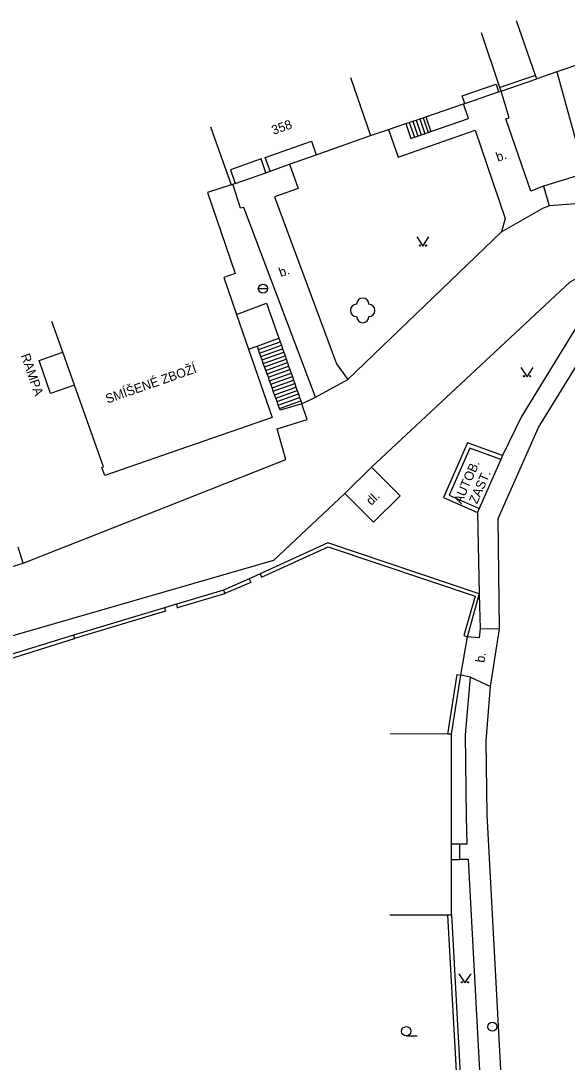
# Model space of a CAD drawing. Extents: x -582162 to -561283, y -1187583 to -1183539.
# Drawn here: x -575012.8 to -574968.4, y -1183822 to -1183737.3 of the extents above; entities that cross this region are included whole.
import ezdxf

# ---------------------------------------------------------------- set-up
doc = ezdxf.new("R2010")
doc.units = 0
for name, color, linetype in [('Vrstva 1', 7, 'Continuous'), ('Vrstva 10', 7, 'Continuous'), ('Vrstva 11', 7, 'Continuous'), ('Vrstva 14', 7, 'Continuous'), ('Vrstva 3', 7, 'Continuous'), ('Vrstva 4', 7, 'Continuous'), ('Vrstva 6', 7, 'Continuous'), ('Vrstva 9', 7, 'Continuous')]:
    doc.layers.add(name, color=color, linetype=linetype)

# ---------------------------------------------------------------- blocks, each defined once
blk = doc.blocks.new('1.079')
at = {"layer": 'Vrstva 1'}
for radius in [0.75, 0.001]:
    blk.add_circle((0, -0.001), radius, dxfattribs=at)
blk = doc.blocks.new('3.130')
at = {"layer": 'Vrstva 1'}
blk.add_circle((0, 0), 0.001, dxfattribs=at)
for centre, start, end in [((0, 1), 0, 180), ((-1, 0), 90, 270), ((1, 0), 270, 90), ((0, -1), 180, 360)]:
    blk.add_arc(centre, 1, start, end, dxfattribs=at)
blk = doc.blocks.new('3.040')
at = {"layer": 'Vrstva 1'}
blk.add_line((0, -0.75), (1.75, -0.75), dxfattribs=at)
blk.add_circle((0, 0), 0.75, dxfattribs=at)
blk = doc.blocks.new('3.140')
at = {"layer": 'Vrstva 1'}
blk.add_lwpolyline([(-1, 1.5), (0, 0), (1, 1.5)], dxfattribs=at)
for centre in [(-0.5, 0.1), (0.5, 0.1)]:
    blk.add_circle(centre, 0.1, dxfattribs=at)
blk = doc.blocks.new('8.110')
at = {"layer": 'Vrstva 1'}
blk.add_line((-0.75, 0), (0.75, 0), dxfattribs=at)
blk.add_circle((0, 0), 0.75, dxfattribs=at)

msp = doc.modelspace()

# ---------------------------------------------------------------- linework, layer by layer
at = {"layer": 'Vrstva 10'}
for points in [[(-574969.26, -1183741.46), (-574966.98, -1183749.72), (-574970.34, -1183750.75)], [(-574970.34, -1183750.75), (-574971.39, -1183751.16), (-574973.41, -1183745.28), (-574973.13, -1183745.19), (-574973.79, -1183743.01)], [(-574982.95, -1183746.14), (-574982.16, -1183748.38), (-574975.92, -1183746.18), (-574973.46, -1183753.37), (-574973.76, -1183754.46)], [(-574946.48, -1183746.19), (-574952.52, -1183749.26), (-574956.03, -1183751.39), (-574956.56, -1183751.65), (-574957.12, -1183751.84), (-574957.71, -1183751.95), (-574958.3, -1183751.99), (-574958.9, -1183751.94), (-574959.48, -1183751.81), (-574960.04, -1183751.61), (-574969.88, -1183752.34)], [(-574991, -1183748.97), (-574990.3, -1183750.94), (-574992.21, -1183751.62), (-574987.18, -1183765.2), (-574986.27, -1183766.48)], [(-574988.88, -1183767.91), (-574994.71, -1183752.49), (-574994.98, -1183752.54), (-574995.6, -1183750.59)], [(-574970.34, -1183750.75), (-574969.88, -1183752.34)], [(-574973.76, -1183754.46), (-574970.36, -1183752.51), (-574969.88, -1183752.34)], [(-574986.27, -1183766.48), (-574973.76, -1183754.46)], [(-574965.4, -1183758.48), (-574965.57, -1183758.39), (-574966, -1183758.22), (-574966.45, -1183758.13), (-574966.91, -1183758.12), (-574967.36, -1183758.19), (-574967.8, -1183758.34), (-574968.2, -1183758.56), (-574984.34, -1183773.6)], [(-574973.93, -1183786.74), (-574974.04, -1183777.79), (-574970.76, -1183770.38), (-574964.37, -1183760), (-574964.42, -1183759.74), (-574964.57, -1183759.36), (-574964.79, -1183759.01), (-574965.07, -1183758.72), (-574965.4, -1183758.48)], [(-574965.4, -1183758.48), (-574972.13, -1183769.48), (-574973.68, -1183772.66)], [(-574995.3, -1183761.19), (-574992.86, -1183760.26), (-574991.86, -1183763.12)], [(-575008.48, -1183766.93), (-575010.42, -1183767.6), (-575011.34, -1183764.92), (-575009.42, -1183764.26)], [(-574988.88, -1183767.91), (-574986.27, -1183766.48)], [(-575000, -1183776.42), (-574991.29, -1183772.97), (-574992, -1183770.49), (-574989.56, -1183769.73), (-574990.01, -1183768.44)], [(-574990.01, -1183768.44), (-574988.88, -1183767.91)], [(-574973.68, -1183772.66), (-574976.52, -1183771.62), (-574978.49, -1183776.07), (-574975.72, -1183777.29)], [(-574973.82, -1183772.98), (-574976.34, -1183772.07), (-574978.02, -1183775.89), (-574975.58, -1183776.97)], [(-574973.68, -1183772.66), (-574973.82, -1183772.98)], [(-574973.82, -1183772.98), (-574975.58, -1183776.97)], [(-574984.34, -1183773.6), (-574986.5, -1183775.74)], [(-574984.34, -1183773.6), (-574982.01, -1183775.94), (-574984.17, -1183778.08), (-574986.5, -1183775.74)], [(-574986.5, -1183775.74), (-574992.29, -1183781.19), (-575000, -1183783.42)], [(-575012.64, -1183781.42), (-575000, -1183776.42)], [(-574975.58, -1183776.97), (-574975.72, -1183777.29)], [(-574975.72, -1183777.29), (-574975.57, -1183783.9)], [(-575012.64, -1183781.42), (-575013.05, -1183780.11)], [(-575021.78, -1183784.25), (-575012.64, -1183781.42)], [(-575000, -1183783.42), (-575046.66, -1183796.9), (-575082.88, -1183807.94), (-575106.87, -1183817.05), (-575126.02, -1183825.3), (-575133.54, -1183828.99)], [(-574975.57, -1183783.97), (-574975.51, -1183786.71)], [(-574975.51, -1183786.71), (-574975.59, -1183787.49), (-574976.54, -1183787.39)], [(-574975.51, -1183786.71), (-574973.93, -1183786.74)], [(-574974.65, -1183791.44), (-574973.93, -1183786.74)], [(-574977.14, -1183804.25), (-574976.56, -1183804.25), (-574976.62, -1183802.02), (-574976.7, -1183795.37), (-574976.29, -1183790.69)], [(-574976.29, -1183790.69), (-574977.08, -1183790.52)], [(-574976.29, -1183790.69), (-574974.65, -1183791.44)], [(-574973.08, -1183836.23), (-574974.94, -1183801.87), (-574975, -1183795.87), (-574974.65, -1183791.44)], [(-574977.84, -1183804.24), (-574977.14, -1183804.25)], [(-574977.14, -1183805.5), (-574977.14, -1183804.25)], [(-574977.84, -1183805.5), (-574977.14, -1183805.5)], [(-574974.8, -1183836.31), (-574976.44, -1183805.52), (-574977.14, -1183805.5)]]:
    msp.add_lwpolyline(points, dxfattribs=at)
at = {"layer": 'Vrstva 4'}
for points in [[(-574971, -1183741.74), (-574972.54, -1183737.3)], [(-574973.89, -1183742.73), (-574975.4, -1183738.28)], [(-574967.19, -1183740.75), (-574969.26, -1183741.46)], [(-574986.03, -1183741.91), (-574984.41, -1183746.64)], [(-574970.9, -1183742.03), (-574971, -1183741.74)], [(-574969.26, -1183741.46), (-574970.9, -1183742.03)], [(-574976.76, -1183744.03), (-574976.97, -1183743.39), (-574974.21, -1183742.45), (-574974, -1183743.08)], [(-574974, -1183743.08), (-574973.79, -1183743.01)], [(-574973.79, -1183743.01), (-574973.89, -1183742.73)], [(-574976.76, -1183744.03), (-574974, -1183743.08)], [(-574979.93, -1183745.11), (-574976.86, -1183744.06)], [(-574976.86, -1183744.06), (-574976.76, -1183744.03)], [(-574981.55, -1183745.66), (-574981.27, -1183745.56)], [(-574981.27, -1183745.56), (-574980.98, -1183745.46)], [(-574980.98, -1183745.46), (-574980.7, -1183745.37)], [(-574980.7, -1183745.37), (-574980.41, -1183745.27)], [(-574980.41, -1183745.27), (-574980.13, -1183745.18)], [(-574980.13, -1183745.18), (-574979.93, -1183745.11)], [(-574997.41, -1183745.92), (-574995.74, -1183750.64)], [(-574984.41, -1183746.64), (-574982.95, -1183746.14)], [(-574982.95, -1183746.14), (-574981.55, -1183745.66)], [(-574992.58, -1183749.53), (-574992.97, -1183748.41), (-574989.21, -1183747.08), (-574988.82, -1183748.2)], [(-574988.82, -1183748.2), (-574984.41, -1183746.64)], [(-574992.92, -1183749.65), (-574993.31, -1183748.53), (-574995.81, -1183749.41), (-574995.42, -1183750.53)], [(-574992.58, -1183749.53), (-574991, -1183748.97)], [(-574991, -1183748.97), (-574988.82, -1183748.2)], [(-574995.42, -1183750.53), (-574992.92, -1183749.65)], [(-574992.92, -1183749.65), (-574992.58, -1183749.53)], [(-574995.74, -1183750.64), (-574997.66, -1183751.26), (-574995.43, -1183757.84), (-574996.34, -1183758.18), (-574995.3, -1183761.19)], [(-574995.74, -1183750.64), (-574995.6, -1183750.59)], [(-574995.6, -1183750.59), (-574995.42, -1183750.53)], [(-574995.3, -1183761.19), (-574994.33, -1183764)], [(-575009.42, -1183764.26), (-575010.31, -1183761.75)], [(-574994.33, -1183764), (-574992.41, -1183769.56), (-575000, -1183772.2)], [(-575008.48, -1183766.93), (-575009.42, -1183764.26)], [(-575000, -1183772.2), (-575006, -1183774.29), (-575006.26, -1183773.63), (-575006.12, -1183773.58), (-575008.48, -1183766.93)], [(-574978.13, -1183795.31), (-574982.83, -1183795.3)], [(-574977.83, -1183795.31), (-574978.13, -1183795.31)], [(-574977.84, -1183804.24), (-574977.83, -1183795.31)], [(-574977.84, -1183805.5), (-574977.84, -1183804.24)], [(-574977.84, -1183810), (-574977.84, -1183805.5)], [(-574982.84, -1183810), (-574978.14, -1183810)], [(-574978.14, -1183810), (-574977.84, -1183810)]]:
    msp.add_lwpolyline(points, dxfattribs=at)
at = {"layer": 'Vrstva 9'}
for points in [[(-574971, -1183741.74), (-574973.89, -1183742.73)], [(-574973.79, -1183743.01), (-574970.9, -1183742.03)], [(-574979.52, -1183746.31), (-574976.45, -1183745.24), (-574976.86, -1183744.06)], [(-574981.27, -1183745.56), (-574980.85, -1183746.77)], [(-574980.98, -1183745.46), (-574980.57, -1183746.67)], [(-574980.7, -1183745.37), (-574980.29, -1183746.58)], [(-574980.41, -1183745.27), (-574980, -1183746.48)], [(-574980.13, -1183745.18), (-574979.72, -1183746.38)], [(-574979.93, -1183745.11), (-574979.52, -1183746.31)], [(-574981.55, -1183745.66), (-574981.14, -1183746.87), (-574980.85, -1183746.77)], [(-574980, -1183746.48), (-574979.72, -1183746.38)], [(-574979.72, -1183746.38), (-574979.52, -1183746.31)], [(-574980.85, -1183746.77), (-574980.57, -1183746.67)], [(-574980.57, -1183746.67), (-574980.29, -1183746.58)], [(-574980.29, -1183746.58), (-574980, -1183746.48)], [(-574993.63, -1183763.75), (-574991.86, -1183763.12)], [(-574991.86, -1183763.12), (-574991.76, -1183763.4)], [(-574994.33, -1183764), (-574993.63, -1183763.75)], [(-574993.53, -1183764.03), (-574993.63, -1183763.75)], [(-574993.53, -1183764.03), (-574991.76, -1183763.4)], [(-574993.43, -1183764.32), (-574993.53, -1183764.03)], [(-574993.43, -1183764.32), (-574991.66, -1183763.69)], [(-574993.33, -1183764.6), (-574991.56, -1183763.97)], [(-574991.76, -1183763.4), (-574991.66, -1183763.69)], [(-574991.66, -1183763.69), (-574991.56, -1183763.97)], [(-574991.56, -1183763.97), (-574991.46, -1183764.25)], [(-574993.33, -1183764.6), (-574993.43, -1183764.32)], [(-574993.23, -1183764.88), (-574993.33, -1183764.6)], [(-574993.23, -1183764.88), (-574991.46, -1183764.25)], [(-574993.13, -1183765.16), (-574993.23, -1183764.88)], [(-574993.13, -1183765.16), (-574991.36, -1183764.54)], [(-574993.02, -1183765.45), (-574991.26, -1183764.82)], [(-574991.46, -1183764.25), (-574991.36, -1183764.54)], [(-574991.36, -1183764.54), (-574991.26, -1183764.82)], [(-574991.26, -1183764.82), (-574991.17, -1183765.09)], [(-574993.02, -1183765.45), (-574993.13, -1183765.16)], [(-574992.92, -1183765.73), (-574993.02, -1183765.45)], [(-574992.92, -1183765.73), (-574991.17, -1183765.09)], [(-574992.82, -1183766.01), (-574992.92, -1183765.73)], [(-574992.82, -1183766.01), (-574991.07, -1183765.39)], [(-574992.72, -1183766.29), (-574990.97, -1183765.67)], [(-574991.17, -1183765.09), (-574991.07, -1183765.39)], [(-574991.07, -1183765.39), (-574990.97, -1183765.67)], [(-574990.97, -1183765.67), (-574990.87, -1183765.96)], [(-574992.72, -1183766.29), (-574992.82, -1183766.01)], [(-574992.62, -1183766.58), (-574992.72, -1183766.29)], [(-574992.62, -1183766.58), (-574990.87, -1183765.96)], [(-574992.52, -1183766.86), (-574992.62, -1183766.58)], [(-574992.52, -1183766.86), (-574990.77, -1183766.24)], [(-574992.42, -1183767.14), (-574990.67, -1183766.52)], [(-574990.87, -1183765.96), (-574990.77, -1183766.24)], [(-574990.77, -1183766.24), (-574990.67, -1183766.52)], [(-574990.67, -1183766.52), (-574990.58, -1183766.8)], [(-574992.42, -1183767.14), (-574992.52, -1183766.86)], [(-574992.32, -1183767.42), (-574992.42, -1183767.14)], [(-574992.32, -1183767.42), (-574990.58, -1183766.8)], [(-574992.21, -1183767.71), (-574992.32, -1183767.42)], [(-574992.21, -1183767.71), (-574990.48, -1183767.09)], [(-574992.11, -1183767.99), (-574990.38, -1183767.37)], [(-574990.58, -1183766.8), (-574990.48, -1183767.09)], [(-574990.48, -1183767.09), (-574990.38, -1183767.37)], [(-574990.38, -1183767.37), (-574990.28, -1183767.65)], [(-574992.11, -1183767.99), (-574992.21, -1183767.71)], [(-574992.01, -1183768.27), (-574992.11, -1183767.99)], [(-574992.01, -1183768.27), (-574990.28, -1183767.65)], [(-574991.91, -1183768.55), (-574992.01, -1183768.27)], [(-574991.91, -1183768.55), (-574990.18, -1183767.94)], [(-574991.81, -1183768.83), (-574990.09, -1183768.22)], [(-574990.01, -1183768.44), (-574991.76, -1183768.97), (-574991.81, -1183768.83)], [(-574990.28, -1183767.65), (-574990.18, -1183767.94)], [(-574990.18, -1183767.94), (-574990.09, -1183768.22)], [(-574990.09, -1183768.22), (-574990.01, -1183768.44)], [(-574991.81, -1183768.83), (-574991.91, -1183768.55)], [(-574975.57, -1183783.9), (-574987.89, -1183779.75), (-574993.39, -1183782.28)], [(-574993.39, -1183782.28), (-574993.27, -1183782.55), (-574987.87, -1183780.07), (-574975.92, -1183784.1), (-574976.83, -1183787.3), (-574976.54, -1183787.39)], [(-574994.27, -1183782.69), (-574996.36, -1183783.6)], [(-574994.27, -1183782.69), (-574994.15, -1183782.97), (-574996.27, -1183783.88)], [(-574993.39, -1183782.28), (-574994.27, -1183782.69)], [(-574996.36, -1183783.6), (-575000, -1183784.68)], [(-574996.36, -1183783.6), (-574996.27, -1183783.88)], [(-575000, -1183784.99), (-574996.27, -1183783.88)], [(-574976.54, -1183787.39), (-574975.57, -1183783.97)], [(-574975.57, -1183783.97), (-574975.57, -1183783.9)], [(-575001.15, -1183785.03), (-575008.56, -1183787.27)], [(-575001.15, -1183785.03), (-575001.07, -1183785.32), (-575008.47, -1183787.55)], [(-575000.2, -1183784.74), (-575001.15, -1183785.03)], [(-575000, -1183784.68), (-575000.2, -1183784.74)], [(-575000.2, -1183784.74), (-575000.12, -1183785.03), (-575000, -1183784.99)], [(-575008.56, -1183787.27), (-575013.91, -1183788.92)], [(-575013.91, -1183788.92), (-575013.82, -1183789.21), (-575008.47, -1183787.55)], [(-575008.56, -1183787.27), (-575008.47, -1183787.55)], [(-574977.08, -1183790.52), (-574976.54, -1183787.39)], [(-574978.13, -1183795.31), (-574977.38, -1183790.47), (-574977.08, -1183790.52)], [(-574977.83, -1183795.31), (-574977.08, -1183790.52)], [(-574979.77, -1183828.76), (-574977.1, -1183828.65), (-574978.14, -1183810)], [(-574977.84, -1183810), (-574976.79, -1183828.93), (-574979.76, -1183829.06)]]:
    msp.add_lwpolyline(points, dxfattribs=at)

# ---------------------------------------------------------------- block references
at = {"layer": 'Vrstva 1', "xscale": 0.5, "yscale": 0.5}
msp.add_blockref('1.079', (-574974.51, -1183819.11), dxfattribs=at)
at = {"layer": 'Vrstva 11', "xscale": 0.5, "yscale": 0.5}
msp.add_blockref('3.130', (-574985.05, -1183760.85), dxfattribs=at)
at = {"layer": 'Vrstva 3', "xscale": 0.5, "yscale": 0.5}
for name, p in [('3.140', (-574980.16, -1183755.62)), ('3.140', (-574971.69, -1183766.25)), ('3.140', (-574976.74, -1183815.55)), ('3.040', (-574981.51, -1183819.48))]:
    msp.add_blockref(name, p, dxfattribs=at)
at = {"layer": 'Vrstva 9', "xscale": 0.5, "yscale": 0.5}
msp.add_blockref('8.110', (-574993.16, -1183759.08), dxfattribs=at)

# ---------------------------------------------------------------- texts
at = {"layer": 'Vrstva 14'}
for s, rotation, p in [('b.', 19.465, (-574974.06, -1183748.77)), ('b.', 19.441, (-574991.71, -1183758.15)), ('RAMPA', 288.927, (-575012.85, -1183764.51)), ('SMÍŠENÉ ZBOŽÍ', 19.188, (-575005.8, -1183768.43)), ('SMÍŠENÉ ZBOŽÍ', 19.188, (-575005.8, -1183768.43)), ('AUTOB.', 66.188, (-574977.02, -1183776.65)), ('ZAST.', 66.188, (-574975.76, -1183776.65)), ('dl.', 44.867, (-574984.34, -1183776.76)), ('b.', 81.264, (-574975.15, -1183789.54))]:
    msp.add_text(s, height=0.75, rotation=rotation, dxfattribs=at).set_placement(p)
at = {"layer": 'Vrstva 6'}
msp.add_text('358', height=0.75, rotation=19.445, dxfattribs=at).set_placement((-574992.3, -1183746.58))

doc.saveas('drawing.dxf')
